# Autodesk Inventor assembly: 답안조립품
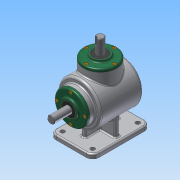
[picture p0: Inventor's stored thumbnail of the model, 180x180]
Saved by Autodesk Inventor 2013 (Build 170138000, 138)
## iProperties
Created: 2016-09
Part Number: 답안조립품
Document SubType Name: Assembly
Designer: Administrator
Author: Administrator
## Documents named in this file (14)
- C:\Users\Administrator\Desktop\460908V1008\답안조립품.iam
- C:\Users\Administrator\Desktop\460908V1008\본체.ipt
- C:\Users\Administrator\Desktop\460908V1008\460908V1008\커버.ipt
- C:\Users\Administrator\Desktop\460908V1008\460908V1008\베어링 6203.ipt
- C:\Users\Administrator\Desktop\460908V1008\460908V1008\오일실 17 32 8.ipt
- C:\Users\Administrator\Desktop\460908V1008\460908V1008\메인 축.ipt
- 메인 축.ipt
- C:\Users\Administrator\Desktop\460908V1008\460908V1008\서브 축.ipt
- 서브 축.ipt
- C:\Users\Administrator\Desktop\460908V1008\460908V1008\메인 베벨기어.ipt
- C:\Users\Administrator\Desktop\460908V1008\460908V1008\키 5x5.ipt
- C:\Users\Administrator\Desktop\460908V1008\460908V1008\키 4x4.ipt
- C:\Users\Administrator\Desktop\460908V1008\460908V1008\서브 베벨기어.ipt
- C:\Users\Administrator\Desktop\460908V1008\460908V1008\M4.ipt
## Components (8 placed, 1 different names)
1. M4:1
2. M4:3
3. M4:4
4. M4:5
5. M4:2
6. M4:6
7. M4:7
8. M4:8
